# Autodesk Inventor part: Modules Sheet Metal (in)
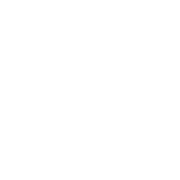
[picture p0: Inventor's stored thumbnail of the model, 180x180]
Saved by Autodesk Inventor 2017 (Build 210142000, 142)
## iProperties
Created: 2014-08
Part Number: Modules Sheet Metal (in)
Material: Generic
Document SubType Name: Sheet Metal
Designer: Wally
Density: 1 g/cm^3
Sheet Metal Rule: Default
Appearance: Default
Author: Wally
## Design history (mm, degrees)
node "Sketch1"
other parameters: "Thickness" = 3.048, "BendRadius" = 3.048 (= Thickness), "BendReliefWidth" = 3.048 (= Thickness), "BendReliefDepth" = 1.524 (= 0.5 x Thickness), "CornerReliefSize" = 12.192 (= 4 x Thickness), "SeamGap" = 0.01, "MinimumRemnant" = 6.096 (= 2 x Thickness), "TransitionRadius" = 3.048 (= BendRadius), "JacobiRadiusSize" = 3.048 (= Thickness), "GapSize" = 3.048 (= Thickness)
